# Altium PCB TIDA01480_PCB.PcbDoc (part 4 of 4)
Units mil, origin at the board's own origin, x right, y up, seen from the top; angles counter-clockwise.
Board outline 2500 x 3500 mil, 6 copper layers (Top Layer, GND Upper, Signal Layer 1, Signal Layer 2, GND Lower, Bottom Layer), stack 63.4 mil thick; 332 components, 140 nets, 983 pads, 692 vias.
Unrouted connection lines stored in the file: 17.
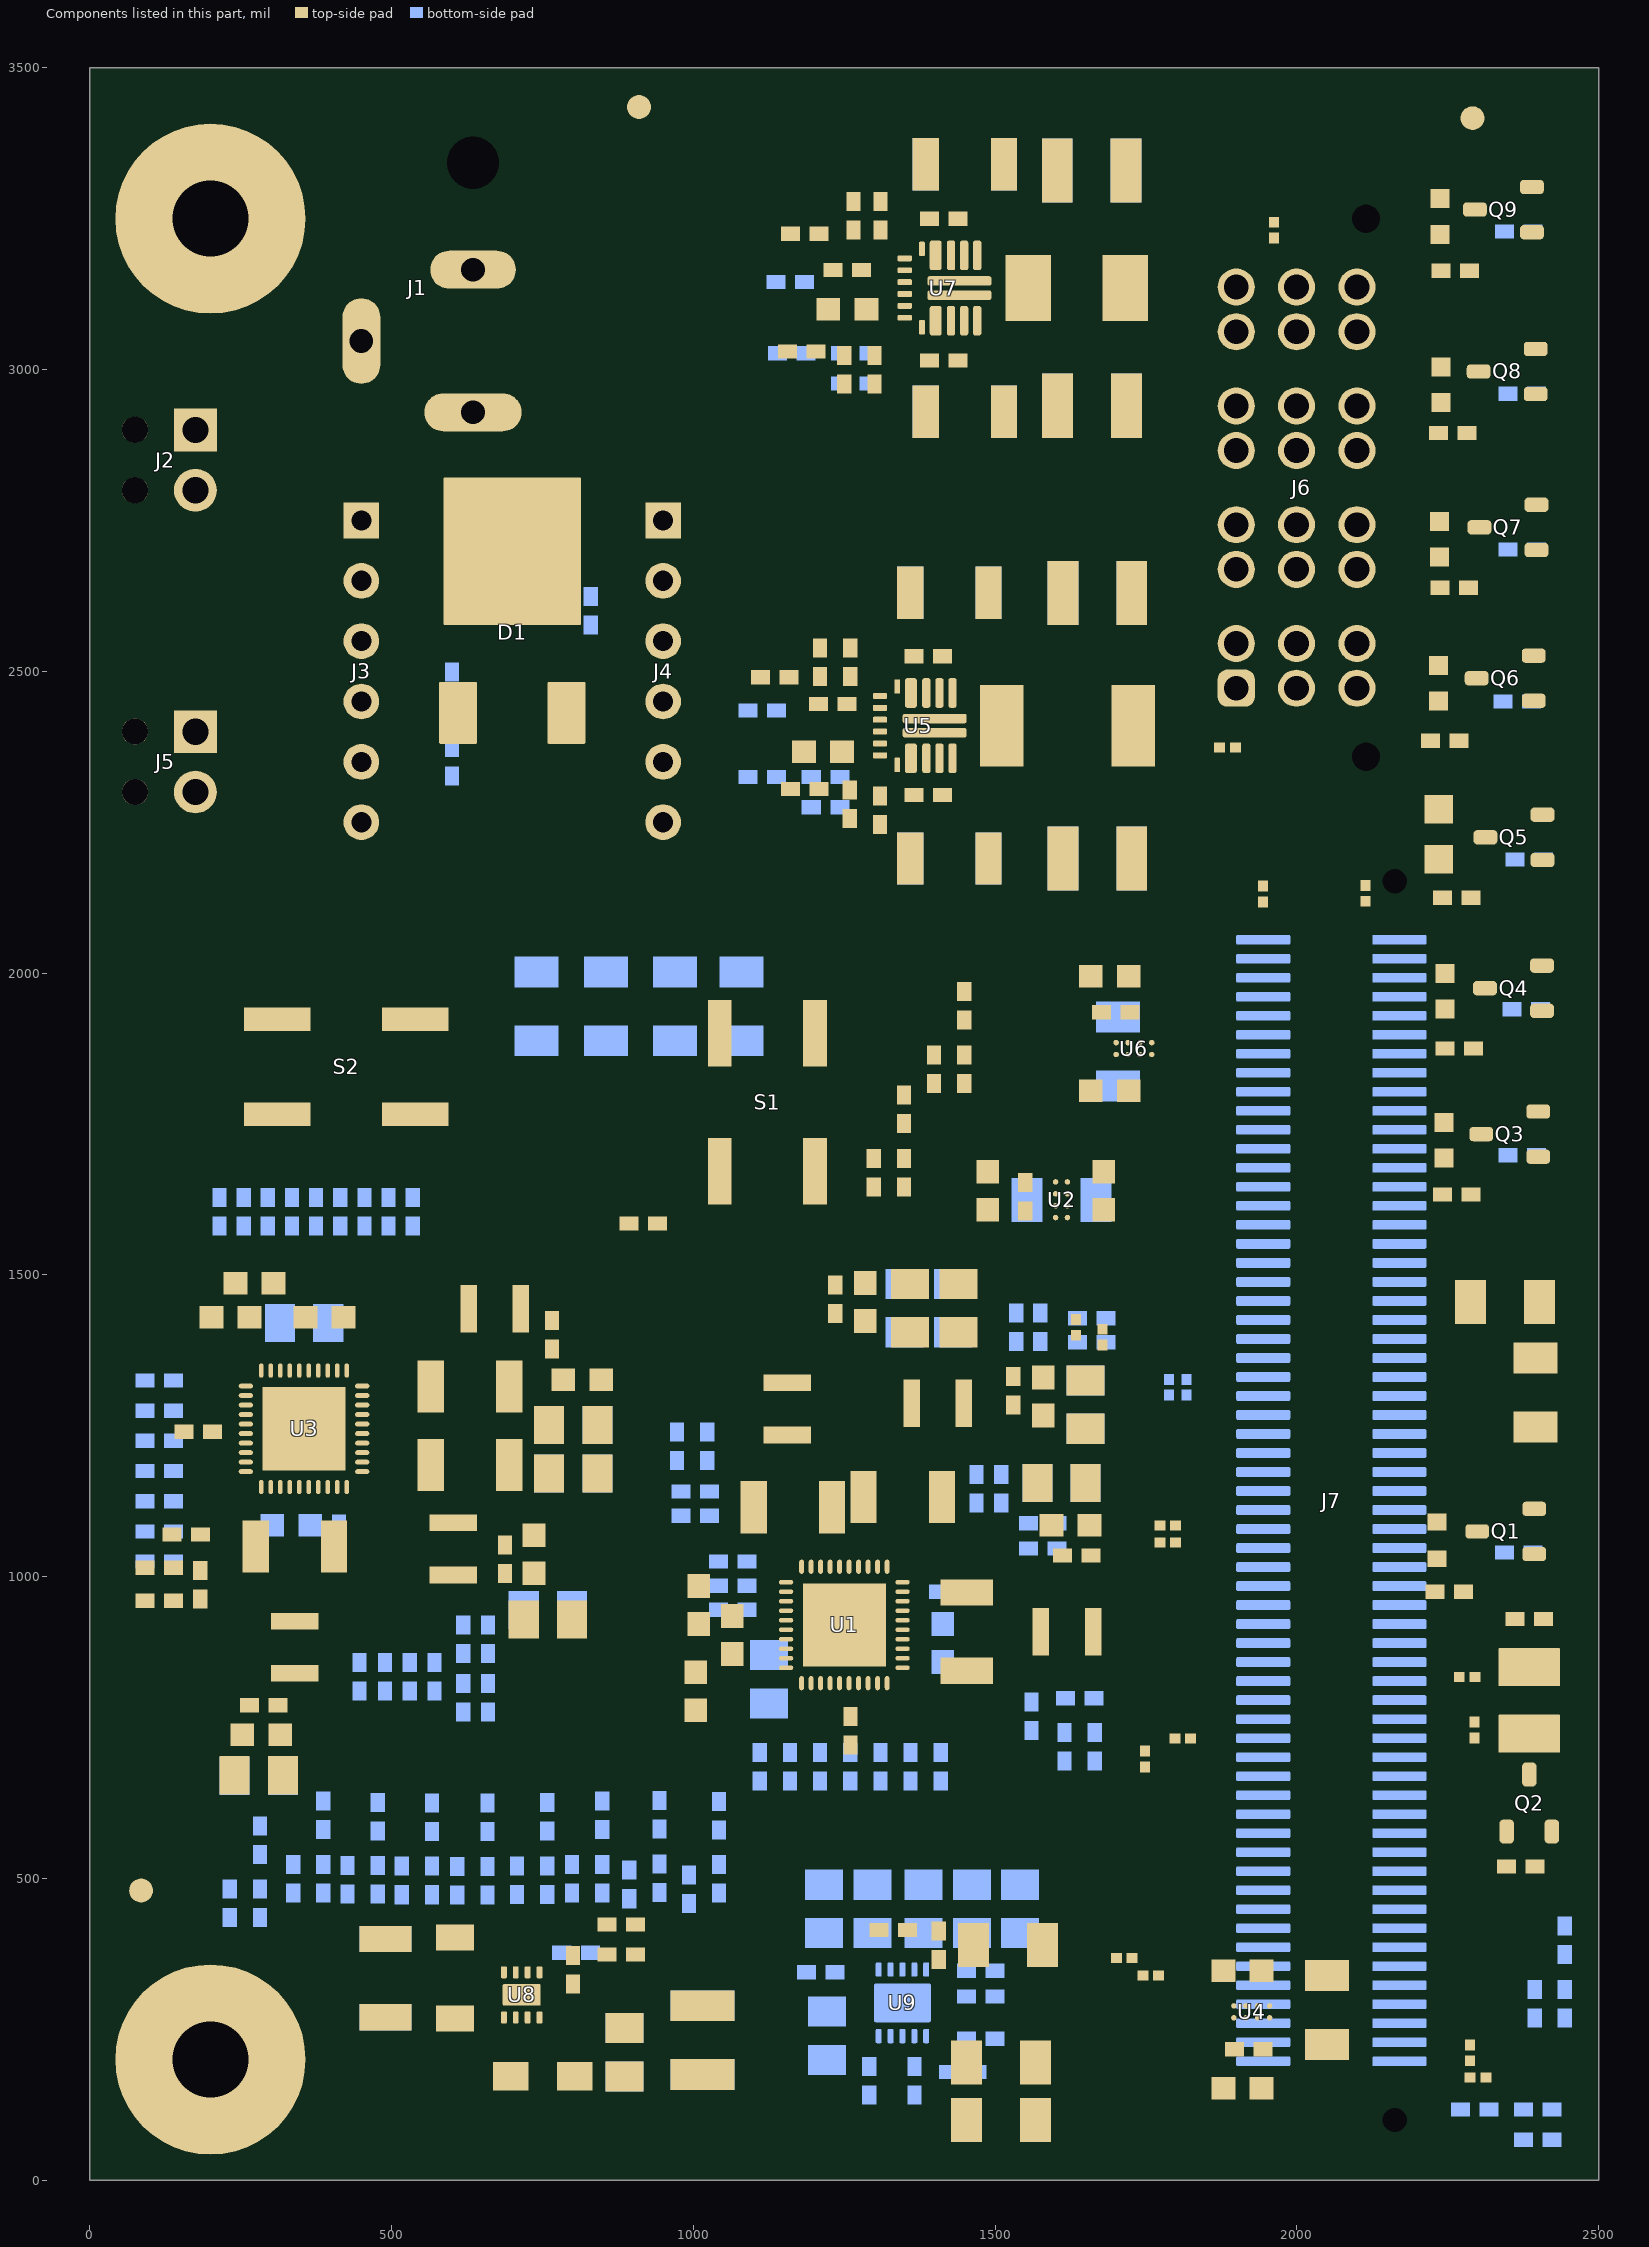
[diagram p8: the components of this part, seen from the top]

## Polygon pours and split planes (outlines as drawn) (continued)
GND on Top Layer "TOP_LAYER_GND_P100" (solid, remove dead copper, pour order 100): 325,1178 325,1135 299,1109 263,1109 240,1086 240,962 297,962 297,1067 310.28,1080.28 338,1108 338,1178
GND on Top Layer "TOP_LAYER_GND_P098" (solid, remove dead copper, pour order 98): 324,1355 324,1311 325,1310 386,1310 386,1360 396,1370 430,1370 469,1409 469,1462 389,1462 389,1393 359,1363 355,1363 355,1326 354,1327 340,1327 340,1355
LDO2B on Top Layer "TOP_LAYER_LDO2B_P096" (solid, remove dead copper, pour order 96): 310,1327 310,1373 334,1397 334,1514.89 382,1515.08 382,1397 345,1360 329,1360 324,1355 324,1327
VSYS on Top Layer "TOP_LAYER_VSYS_P094" (solid, remove dead copper, pour order 94): 307,1328 307,1373 332,1398 332,1545 270,1545 270,1449.98 293,1449.98 293,1328
NetL6_1 on Top Layer "TOP_LAYER_NETL6_1_P092" (solid, remove dead copper, pour order 92): 439,1216 439,1227 440,1228 503,1228 540,1191 540,1136.86 546.93,1129.93 642,1129.93 642,1039 560,1039 532.5,1066.5 503,1096 503,1195 482,1216
NetL4_1 on Top Layer "TOP_LAYER_NETL4_1_P090" (solid, remove dead copper, pour order 90): 438,1274 438,1263 439,1262 498,1262 537,1301 537,1363 576,1402 643.43,1402 643.43,1490 540,1490 520,1452 520,1399 500,1379 500,1293 481,1274
VSYS on Top Layer "TOP_LAYER_VSYS_P088" (solid, remove dead copper, pour order 88): 439,1258 439,1230 509,1230 543,1196 543,1140 609,1140 609,1360 540,1360 540,1300 498,1258
VDCDC2_B on Top Layer "TOP_LAYER_VDCDC2_B_P044" (solid, remove dead copper, pour order 44): 295,860 295,640 383,640 383,780 390,796 392,796 392,843 390,843 383,860
VCC_1or2A on Top Layer "TOP_LAYER_VCC_1OR2A_P060" (solid, remove dead copper, pour order 60): 770,220 770,100 1095.63,100 1094,101.63 1094,220
GND on Top Layer "TOP_LAYER_GND_P086" (solid, remove dead copper, pour order 86): 1070,322 1070,240 959,240 946,227 833,227 810,250 770,250 770,293 787,310 950,310 962,322
NetL9_1 on Top Layer "TOP_LAYER_NETL9_1_P062" (solid, remove dead copper, pour order 62): 698,284 698,241 697,241 651,195 650,195 650,100 740,100 740,242 732,250 715,256 715,284
GND on Top Layer "TOP_LAYER_GND_P084" (solid, remove dead copper, pour order 84): 505,191 445,236 445,297 530,297 559,326 695,326 695,248 638,191
VSYS on Top Layer "TOP_LAYER_VSYS_P028" (solid, remove dead copper, pour order 28): 430,477 430,430 430,340 621,340 631,330 715,330 715,380 704,380 612.99,477
GND on Top Layer "TOP_LAYER_GND_P080" (solid, remove dead copper, pour order 80): 1720,1310 1505,1310 1505,1035 1568,1035 1568,1030 1588,1010 1633,1010 1633,1068 1632,1069 1632,1093.5 1620,1105.5 1620,1125.5 1620,1203 1719,1203 1720,1204
VDCDC2_A on Top Layer "TOP_LAYER_VDCDC2_A_P058" (solid, remove dead copper, pour order 58): 1639,851 1639,1051 1625,1065 1625,1193 1731,1193 1731,877 1705,851
GND on Top Layer "TOP_LAYER_GND_P078" (solid, remove dead copper, pour order 78): 1334,902 1334,891 1336,889 1380,889 1389,880 1389,843 1432,800 1557,800 1557,866 1429,866 1384,903 1336,903
VSYS on Top Layer "TOP_LAYER_VSYS_P022" (solid, remove dead copper, pour order 22): 1333,924 1389,924 1430,952 1555,952 1555,1030 1439,1030 1384,975 1384,949 1368,933 1333,933
NetL2_1 on Top Layer "TOP_LAYER_NETL2_1_P056" (solid, remove dead copper, pour order 56): 1334,907 1385,907 1400,898 1433,870 1463,870 1520,870 1520,869.2 1529.2,860 1591.41,860 1591.41,950 1499,950 1499,943 1426,943 1388,918 1334,918
VSYS on Top Layer "TOP_LAYER_VSYS_P014" (solid, remove dead copper, pour order 14): 1167,869 1167,860 1151,860 1129.62,852.32 1082,852.32 1022.7,852.32 990,870 953,870 953,892 1045.82,892 1083.23,892 1083.23,880.77 1092,872 1149.31,872 1151.31,870 1166,870
VLDO2A_3V3 on Top Layer "TOP_LAYER_VLDO2A_3V3_P054" (solid, remove dead copper, pour order 54): 1166,885 1166,876 1088.87,876 1081.46,897 947.42,897 947.42,956 1090,956 1090,919 1094,915 1096,913 1120,906 1141,885
VLDO1A_1V8 on Top Layer "TOP_LAYER_VLDO1A_1V8_P052" (solid, remove dead copper, pour order 52): 1165,854 1022,854 1022,875.02 950,875.02 950,807 1120,807 1133,807 1165,839
VDCDC3_A on Top Layer "TOP_LAYER_VDCDC3_A_P042" (solid, remove dead copper, pour order 42): 1430.59,1363.77 1430.59,1244.11 1500,1243.88 1500,1305 1505,1310 1555,1310 1565,1300 1608.54,1300 1621.46,1287.09 1621.46,1285 1720,1285 1720,1365 1431.82,1365
NetL3_1 on Top Layer "TOP_LAYER_NETL3_1_P050" (solid, remove dead copper, pour order 50): 1387.28,1330.31 1387.28,1244.23 1383,1194 1383,1091 1280,1045.21 1280,1000 1262,1000 1262,1058.74 1308,1089 1310,1135 1346,1244.23 1346,1330.31
VDCDC1_A on Top Layer "TOP_LAYER_VDCDC1_A_P034" (solid, remove dead copper, pour order 34): 1045,1330 1045,1423.19 1086.81,1465 1256.32,1465 1271.32,1450 1480,1450 1480,1369 1260,1369 1260,1330
VSYS on Top Layer "TOP_LAYER_VSYS_P018" (solid, remove dead copper, pour order 18): 1415,3160 1385,3160 1385,3220 1350,3255 1350,3485 1485,3485 1485,3294.88 1465.12,3275 1430,3275 1430,3225 1420,3225 1415,3220
GND on Top Layer "TOP_LAYER_GND_P006" (solid, remove dead copper, pour order 6): 1415,3160 1415,3225 1423,3233 1423,3273 1430,3280 1500,3280 1500,3485 1710,3485 1710,3275 1660,3225 1490,3225 1480,3165
VCC_8A on Top Layer "TOP_LAYER_VCC_8A_P000" (solid, remove dead copper, pour order 0): 1670,3485 1670,2886.85 1771,2886.85 1771,3485
GND on Top Layer "TOP_LAYER_GND_P002" (solid, remove dead copper, pour order 2): 1415,3110 1415,3045 1428.19,3031.81 1429.27,3031.81 1429.27,2990.73 1430,2990 1500,2990 1500,2758 1710,2758 1710,2995 1660,3045 1490,3045 1480,3105
VSYS on Top Layer "TOP_LAYER_VSYS_P024" (solid, remove dead copper, pour order 24): 1415,3105 1390,3105 1390,3045 1355,3010 1355,2780 1495,2780 1495,2965.12 1470.12,2990 1435,2990 1435,3040 1425,3040 1415,3045
NetC68_2 on Top Layer "TOP_LAYER_NETC68_2_P048" (solid, remove dead copper, pour order 48): 1385,3155 1480,3155 1490,3165 1490,3185 1510,3205 1595,3205 1595,3065 1510,3065 1490,3085 1490,3104.1 1479.1,3115 1385,3115
NetC51_2 on Top Layer "TOP_LAYER_NETC51_2_P046" (solid, remove dead copper, pour order 46): 1345,2430 1440,2430 1450,2440 1450,2460 1470,2480 1550,2480 1550,2340 1470,2340 1450,2360 1450,2379.1 1439.1,2390 1345,2390
GND on Top Layer "TOP_LAYER_GND_P076" (solid, remove dead copper, pour order 76): 1562.76,1635 1450,1635 1450,1725 1725,1725 1725,1650 1580,1650
VCC_PSPLL on Top Layer "TOP_LAYER_VCC_PSPLL_P036" (solid, remove dead copper, pour order 36): 1612,1644.13 1612,1564.3 1709.3,1564.3 1732,1587 1732,1640 1661.85,1640 1661.3,1639.45 1656.61,1644.13
VDCDC1_A on Top Layer "TOP_LAYER_VDCDC1_A_P030" (solid, remove dead copper, pour order 30): 1565,1628 1581.13,1644.13 1608,1644.13 1608,1564 1450,1564.21 1450,1628
VSYS on Top Layer "TOP_LAYER_VSYS_P020" (solid, remove dead copper, pour order 20): 1263,1000 1263,1059.36 1306.46,1088.75 1306.46,1225 1203.18,1225 1210,1075 1220,1065 1237,1048 1237,1000
LDO1B__or__VPS_MTRAVTT on Top Layer "TOP_LAYER_LDO1B__OR__VPS_MTRAVTT_P040" (solid, remove dead copper, pour order 40): 288,1449 288,1329 278,1329 262,1355 198,1355 198,1449
GND on Top Layer "TOP_LAYER_GND_P070" (solid, remove dead copper, pour order 70): 283,846 283,609 182,609 182,846
VSYS on Top Layer "TOP_LAYER_VSYS_P026" (solid, remove dead copper, pour order 26): 1375,2380 1350,2380 1350,2320 1315,2285 1315,2055 1455,2055 1455,2240.12 1430.12,2265 1395,2265 1395,2315 1385,2315 1375,2320
GND on Top Layer "TOP_LAYER_GND_P064" (solid, remove dead copper, pour order 64): 1375,2385 1375,2320 1388.19,2306.81 1389.27,2306.81 1389.27,2265.73 1390,2265 1460,2265 1460,2060 1670,2060 1670,2270 1620,2320 1450,2320 1440,2380
VCC_12A on Top Layer "TOP_LAYER_VCC_12A_P032" (solid, remove dead copper, pour order 32): 1685,2687 1685,1878 1780,1878 1780,2687
GND on Top Layer "TOP_LAYER_GND_P066" (solid, remove dead copper, pour order 66): 1375,2435 1375,2500 1388.19,2513.19 1389.27,2513.19 1389.27,2554.27 1390,2555 1460,2555 1460,2760 1670,2760 1670,2550 1620,2500 1450,2500 1440,2440
VSYS on Top Layer "TOP_LAYER_VSYS_P016" (solid, remove dead copper, pour order 16): 1375,2435 1345,2435 1345,2495 1310,2530 1310,2760 1450,2760 1450,2574.88 1425.12,2550 1390,2550 1390,2500 1380,2500 1375,2495
VSYS on Top Layer "TOP_LAYER_VSYS_P162" (solid, remove dead copper, pour order 162): 0,3500 1625,3500 1625,965 510,965 510,1830 0,1830
VCC_12A_LS3 on Top Layer "TOP_LAYER_VCC_12A_LS3_P104" (solid, remove dead copper, pour order 104): 1684,1878 1684,1776 1825,1776 1899,1791.29 1899,1817.12 1856,1850 1759,1850 1745,1878
VCC_12A on Top Layer "TOP_LAYER_VCC_12A_P106" (solid, remove dead copper, pour order 106): 2120,2599 2151,2568 2151,2450 2120,2419 2120,2415 1830,2415 1776,2361 1776,2649 1826,2599
VCC_8A on Top Layer "TOP_LAYER_VCC_8A_P108" (solid, remove dead copper, pour order 108): 2104,3189 2135,3158 2135,3040 2104,3009 2104,3005 1814,3005 1760,2951 1760,3239 1810,3189
GND on Top Layer "TOP_LAYER_GND_P110" (solid, remove dead copper, pour order 110): 2113,2998 2157,2954 2157,2655 2115,2613 1831,2613 1795,2649 1795,2695 1662,2695 1663,2696 1663,2880 1779,2880 1780,2879 1780,2951 1827,2998
VDCDC3_B on Top Layer "TOP_LAYER_VDCDC3_B_P112" (solid, remove dead copper, pour order 112): 550,1030 550,980 620,910 765,910 767,908 767,1015 752,1030
VDCDC1_B on Top Layer "TOP_LAYER_VDCDC1_B_P114" (solid, remove dead copper, pour order 114): 691,1490 690,1489 690,1402 788,1402 820,1370 820,1308 810,1298 810,1085 900,1085 900,1130 900,1410 853,1410 773,1490
GND on Top Layer "TOP_LAYER_GND_P116" (solid, remove dead copper, pour order 116): 645,1393 648,1396 782,1396 810,1368 810,1311 811,1310 800,1299 800,1080 850,1030 850,901 851,900 771,900 770,901 770,1028 758,1040 660,1040 660,1226 645,1241
NetD1_1 on Top Layer "TOP_LAYER_NETD1_1_P008" (solid, remove dead copper, pour order 8): 1000,2800 815,2800 815,2640 750,2575 690,2485 578.35,2485 578.35,2370 900,2370 900,2500 1000,2500
NetJ3_1 on Top Layer "TOP_LAYER_NETJ3_1_P010" (solid, remove dead copper, pour order 10): 25,2350 300,2350 450,2500 460,2500 500,2540 500,2820 490,2810 275,2810 275,2705 200,2630 115,2630 25,2540
VSYS on Bottom Layer "BOTTOM_LAYER_VSYS_P186" (solid, remove dead copper, pour order 186): 0,3500 2500,3500 2500,0 0,0
VCC_1or2A on Bottom Layer "BOTTOM_LAYER_VCC_1OR2A_P148" (solid, remove dead copper, pour order 148): 1995,245 2005,255 2005,330 1995,340 1810,340 1715,245 1715,240 1825,240 1830,245
VDCDC2_B on Bottom Layer "BOTTOM_LAYER_VDCDC2_B_P140" (solid, remove dead copper, pour order 140): 1319,87 1626,87 1643,104 1935,104 2074,243 2245.29,243 2262,226.29 2262,198 2245.29,181.29 2120,181.29 1972,32 1319,32
GND on Bottom Layer "BOTTOM_LAYER_GND_P082" (solid, remove dead copper, pour order 82): 1689,1278 1570,1278 1515.5,1223.5 1515.5,1192.5 1545,1163 1545,1123 1569,1123 1579.6,1123 1619,1123 1619,1200 1631,1212 1688,1212 1689,1213
GND on Bottom Layer "BOTTOM_LAYER_GND_P166" (solid, remove dead copper, pour order 166): 325,1105.12 255,1105 255,1010 240,995 240,960 295,960 295,1036.3 325,1066.3
GND on Bottom Layer "BOTTOM_LAYER_GND_P170" (solid, remove dead copper, pour order 170): 750,326 750,290 688,290 683,285 683,235 633,185 495,185 444,236 444,330 454,340 619,340 633,326
GND on Bottom Layer "BOTTOM_LAYER_GND_P172" (solid, remove dead copper, pour order 172): 283,837 283,608 182,608 182,837
VDCDC3_B on Bottom Layer "BOTTOM_LAYER_VDCDC3_B_P174" (solid, remove dead copper, pour order 174): 685,986 749,986 760,975 760,875 750,865 685,865
GND on Bottom Layer "BOTTOM_LAYER_GND_P176" (solid, remove dead copper, pour order 176): 840,986 776,986 765,975 765,875 785,855 840,855
VDCDC2_B on Bottom Layer "BOTTOM_LAYER_VDCDC2_B_P182" (solid, remove dead copper, pour order 182): 295,815 295,649 383,649 383,780 392,789 392,815
GND on GND Upper "GND_UPPER_GND_P152" (solid, remove dead copper, pour order 152): 0,3500 2500,3500 2500,0 0,0
GND on GND Lower "GND_LOWER_GND_P156" (solid, remove dead copper, pour order 156): 0,3500 2500,3500 2500,0 0,0
VSYS on Signal Layer 2 "SIGNAL_LAYER_2_VSYS_P164" (solid, remove dead copper, pour order 164): 0,3500 2500,3500 2500,0 0,0
VSYS on Signal Layer 1 "SIGNAL_LAYER_1_VSYS_P184" (solid, remove dead copper, pour order 184): 0,3500 2500,3500 2500,0 0,0

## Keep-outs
Keep-Out Layer:
  text ".Layer_Name" at 577,-858.49 h60

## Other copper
Top Layer:
  rectangle net VSYS: 2220,1405 2345,1585
  rectangle net GND: 1837,326 1899,372
  rectangle net GND: 1825,121 1913,237
  rectangle net VTT: 1555,380 1660,435
  rectangle net VDCDC2_B: 482,32 1418,87
  text ".Layer_Name" at 577,-858.49 h60
Bottom Layer:
  rectangle net VDCDC3_A: 1618,1300 1726,1354
  rectangle net VSYS: 439,373 656,447.17
  rectangle net VSYS: 1312,2587 1381,2713
  rectangle net VDCDC1_A: 1444,1565 1574,1659
  rectangle net VCC_PSPLL: 1638,1565 1714,1667
  rectangle net VCC_12A_LS3: 1661,1785 1786,1849
  rectangle net VCC_12A: 1666,1901 1784,1976.3
  rectangle net VSYS: 1318,2112 1387,2236
  rectangle net GND: 1463,2093 1655,2298
  rectangle net VCC_12A: 1687,2092 1779,2243.15
  rectangle net VCC_8A: 1684,2875 1770,2994
  rectangle net GND: 1485,2814 1663,3046
  rectangle net VSYS: 1354,2815 1440,3040
  rectangle net VSYS: 1350,3226 1414,3437
  rectangle net GND: 1489,3263 1649,3440
  rectangle net VCC_8A: 1671,3270 1774,3424
  rectangle net GND: 1222,1460 1464,1550
  rectangle net VDCDC1_A: 1233,1376 1464,1451
  rectangle net VDCDC2_A: 1625,1118 1730,1187
  rectangle net VDCDC1_B: 800,1125 893,1300
  rectangle net GND: 675,1105 790,1297.46
  rectangle net VCC_12A: 1696,2535 1785,2683
  rectangle net GND: 1460,2510 1640,2760
  text ".Layer_Name" at 577,-858.49 h60

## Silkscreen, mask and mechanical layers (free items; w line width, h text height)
Top Overlay:
  drawing of 163 lines, arcs and shapes, not listed
  text "2.5mm ID, 5.5mm OD" at 834,3360 h40 r270
  text "5V, 6A min. (30W)" at 878,3336 h40 r270
  text "8A Sns (Near)" at 1915,3195 h40 r90
  text "LDO1-A PG" at 2467,3139 h40 r90
  text "5V IN (+)" at 100,2990 h40
  text "8A Discrete Buck" at 1080,2960 h50 r90
  text "U7 PG (8A)" at 2465,2875 h40 r90
  text "GND (-)" at 120,2685 h40
  text "U5 PG (12A)" at 2464,2624 h40 r90
  text "HV Input (+)" at 110,2490 h40
  text "VDDR PG" at 2471,2418 h40 r90
  text "Near" at 1909,2343 h40 r270
  text "12A Buck Sns" at 1971,2340.74 h40 r270
  text "AIC insert" at 560,2315 h60
  text "(HV--> 5V Pre-reg)" at 515,2265 h50
  text "Far" at 1885,2200 h40 r270
  text "GND (-)" at 110,2190 h40
  text "(DDR Term)" at 2471,2185 h40 r90
  text "U9 PG" at 2473,2071 h40 r90
  text "'.PRJ_Number'.PCB_Rev-" at 30,2065 h108.27
  text "12A Discrete Buck" at 1070,2017.09 h50
  text "8A Sns (Far)" at 2080,2005 h40 r90
  text "EN LS3" at 1235,1965 h40
  text "U8 PG" at 2474,1917 h40 r90
  text "DCDC1-A PG" at 2475,1609 h40 r90
  text "PMIC2 (B)" at 90,1565 h60
  text "PMIC1 (A)" at 1005,1565 h60
  text "EN LS1" at 1305,1565 h40
  text "5V" at 2275,1349 h40
  text "3.3V" at 2313,1246 h40 r90
  text "VLED Sel" at 2250,1225 h40 r90
  text "DCDC2-A Sns" at 1734.26,1175 h40
  text "Near" at 1745,1130 h40
  text "Far" at 1744.16,1005 h40
  text "VSYS PG" at 2484,986 h40 r90
  text "Near" at 2210,775 h40
  text "Near" at 1755,745 h40 r90
  text "VSYS Fault" at 2485,725 h40 r90
  text "Far" at 1805,670 h40
  text "Far" at 2260,670 h40 r90
  text "DCDC3-B Sns" at 2185,585 h40 r90
  text "DCDC1-B Sns" at 1685,572 h40
  text "VTT Res Div" at 1330,545 h50
  text "1 or 2A Discrete Buck" at 545.35,475 h50
  text "1o2A Dscrt Sns" at 1650,427 h40
  text "Far" at 1780,361 h40 r90
  text "Near" at 1630,330 h40
  text "Far" at 2340,251 h40 r90
  text "VDDR Sel" at 1616,231 h40
  text "LED Indicators" at 2470,230 h40 r90
  text "U4 Bypass" at 2135,195 h40 r90
  text "1o2A dscrt" at 1615,160 h40
  text "Near" at 2340,117.21 h40
  text "DCDC2-B Sns" at 2255,115 h40 r90
  text "DCDC2-B" at 1615,112 h40
  text ".Layer_Name" at 577,-858.49 h60
Bottom Overlay:
  lines w4: 121,1360 121,1398 ; 136,1595 153,1612 172,1612 ; 180,560 190,550 210,530 ; 305,350 315,340 370,340 380,350 ; 345,330 355,320 365,310 380,295 ; 370,975 405,975 415,965 ; 415,265 415,350 425,360 425,410 ; 416,955 421,960 426,965 486,965 491,965 496,960 ; 420,430 455,430 465,440 ; 505,965 510,970 570,970 575,970 580,965 ; 530,975 530,990 ; 565,345 575,335 575,325 575,265 ; 580,1117 580,1107 596,1091 596,1090 ; 600,350 610,340 665,340 675,350 ; 631,1036 639.5,1027.5 ; 635,285 635,330 ; 685,345 695,335 750,335 760,345 ; 715,255 715,325 ; 750,1822 750,1842 ; 790,735 800,745 855,745 865,735 ; 850,441 850,435 860,425 ; 850,755 850,810 860,820 865,825 ; 855,1820 855,1837 ; 890,755 900,765 955,765 965,755 ; 925,775 925,820 ; 975,748.98 985,758.98 1040,758.98 1050,748.98 ; 975,1820 975,1840 ; 985.3,825 996.3,814 996.3,770 ; 1053,1179 1059,1173 1060,1173 ; 1060,1163 1060,1173 ; 1076,1189 1070,1183 1060,1173 ; 1080,1818 1080,1835 ; 1179,968 1187,968 1192,963 1203,952 ; 1241,842 1254,842 1274.78,821.22 1274.78,813 ; 1408,1197 1419,1186 1438,1186 ; 1418,1085 1435,1068 1516,1068 ; 1572,867 1572,847 1584,835 ; 1577,828 1584,835 ; 1594,835 1584,835 ; 1597,1483 1606,1474 1623,1474 ; 1699,1473 1761,1473 ; 1785,1266.94 1785,1284.47 ; 1815,1268 1815,1284.6 ; 1845.52,1217 1845.52,1417 ; 2250,182 2266,166 ; 2344,390 2354,380 ; 670,1645 670,2100 685,2115 775,2115 1010,2115 1130,2115 1150,2095 1150,1645 1140,1635 680,1635 670,1645
  lines w10: 1110,97 1665,97 1665,581 1110,581 1110,97
  text "VIO Select" at 1040,2125 h60
  text "U6 Bypass" at 1770,1795 h40 r270
  text "(3.3V)" at 826,1699 h40 r270
  text "U2 Bypass" at 1690,1690 h40
  text "LDO2-A" at 860,1670 h40 r270
  text "DCDC2-B" at 737,1652 h40 r270
  text "DCDC3-A" at 1066,1651 h40 r270
  text "1o2A dscrt" at 964,1645 h40 r270
  text "DCDC3-A FB" at 1772,1467 h40 r270
  text "PMIC2 (B) IOs" at 101,1407 h40 r270
  text "Far" at 1805,1210 h40 r270
  text "DCDC3-A Sns" at 1850.69,1208.17 h40 r270
  text "DCDC1-A Comp" at 1430,1203 h40
  text "DCDC1-A FB" at 1081,1192 h40 r270
  text "Near" at 1770,1185 h40 r270
  text "DCDC3-B FB" at 569,1125 h40 r270
  text "VSYS Comp" at 1428,1095 h40
  text "VDDR Comp" at 519,994 h40 r270
  text "LDO1-A Comp" at 365,955 h40
  text "DCDC2-A FB" at 1729,872 h40
  text "PMIC1 (A) IOs" at 1209,841 h40 r270
  text "EN DCDC2-A" at 865,835 h40 r270
  text "EN DCDC1-A" at 910,835 h40 r270
  text "EN LDOs-A" at 970,835 h40 r270
  text "EN LDOs-B" at 148,573 h40 r270
  text "EN LS2" at 2320,400 h40 r270
  text "EN DDR Term" at 2235,190 h40 r270
  text "EN DCDC3-B" at 376,66 h40 r270
  text "EN DCDC1-B" at 559,43 h40 r270
  text "EN 1o2A Dscrt" at 625,43 h40 r270
  text "EN DCDC2-B" at 415,42 h40 r270
  text "EN DCDC3-A" at 693,37 h40 r270
  text ".Layer_Name" at 577,-858.49 h60
Top Paste:
  text ".Layer_Name" at 577,-858.49 h60
Bottom Paste:
  text ".Layer_Name" at 577,-858.49 h60
Top Solder:
  text ".Layer_Name" at 577,-858.49 h60
  text ".Layer_Name" at 577,-858.49 h60
Bottom Solder:
  text ".Layer_Name" at 577,-858.49 h60
Drill Guide:
  text ".Layer_Name" at 577,-858.49 h60
M1 Board Outline:
  the board outline again, w10
  text ".Layer_Name" at 577,-858.49 h60
M2 Board Dimensions:
  rectangle: 125,-400 500,-275
  rectangle: 0,-275 125,-150
  lines w7: 0,-275 1000,-275 ; 125,-400 125,-150 ; 250,-400 250,-150 ; 500,-400 500,-150 ; 750,-400 750,-150 ; 0,-400 0,-150 1000,-150 1000,-400 0,-400
  text ".Layer_Name" at 577,-858.49 h60
M3 3D STEP Top:
  text ".Layer_Name" at 577,-858.49 h60
M4 3D STEP Bottom:
  text ".Layer_Name" at 577,-858.49 h60
M5 Assembly Top:
  lines w10: -292,-930.17 6308,-930.17 ; -292,-726.83 6310,-726.83 ; -292,-523.5 -292,-1133.5 3713,-1133.5 6310,-1133.5 6310,-523.5 -291.5,-523.5 -291.5,-1133.5 1284,-1133.5 ; 2173,-1133.5 2173,-523.5 ; 3440,-726.83 3440,-523.5 ; 4280,-726.83 4280,-523.5 ; 4902,-1140 4902,-937.17
  text "COMPONENTS MARKED 'DNP' SHOULD NOT BE POPULATED." at 1153.5,-318.5 h60
  text "ASSEMBLY VARIANT:" at 1153,-434 h60
  text ".VariantName" at 2189,-434 h60
  text "PCB VIEWED FROM TOP SIDE" at -228.5,-655.67 h60
  text "BOARD #:" at 2248,-655.67 h60
  text ".PRJ_Number" at 2793.5,-655.67 h60
  text "REV:" at 3638,-655.67 h60
  text ".PCB_Rev" at 3929.5,-655.67 h60
  text "SVN REV:" at 4476,-655.67 h60
  text ".VersionControl_RevNumber" at 4982,-655.67 h60
  text "TID #:" at 2248,-859 h60
  text ".TID" at 2793.5,-859 h60
  text "PLOT NAME =" at -228.5,-1064.34 h60
  text ".plot_File_Name" at 577,-1064.34 h60
  text "GENERATED    :" at 2250,-1064.34 h60
  text ".Print_Date" at 3119.5,-1064.34 h60
  text ".Print_Time" at 3848.5,-1064.34 h60
  text "TEXAS INSTRUMENTS" at 5113,-1064.34 h60
M6 Assembly Bottom:
  lines w10: -292.5,-727.33 6309.5,-727.33 ; -290.5,-930.67 6309.5,-930.67 ; 1115.5,-1140.5 1115.5,-937.67 ; 1737.5,-727.33 1737.5,-524 ; 2577.5,-727.33 2577.5,-524 ; 3844.5,-1134 3844.5,-524 ; 4733.5,-1134 6309,-1134 6309,-524 -292.5,-524 -292.5,-1134 2304.5,-1134 6309.5,-1134 6309.5,-524
  text "COMPONENTS MARKED 'DNP' SHOULD NOT BE POPULATED." at 6102,-318 h60
  text ".VariantName" at 5058,-434 h60
  text "ASSEMBLY VARIANT:" at 6097,-434 h60
  text ".VersionControl_RevNumber" at 1035.5,-656.17 h60
  text "SVN REV:" at 1541.5,-656.17 h60
  text ".PCB_Rev" at 2088,-656.17 h60
  text "REV:" at 2379.5,-656.17 h60
  text ".PRJ_Number" at 3224,-656.17 h60
  text "BOARD #:" at 3769.5,-656.17 h60
  text "PCB VIEWED FROM BOTTOM SIDE" at 6246,-656.17 h60
  text ".TID" at 3224,-859.5 h60
  text "TID #:" at 3769.5,-859.5 h60
  text "TEXAS INSTRUMENTS" at 904.5,-1064.84 h60
  text ".Print_Time" at 2169,-1064.84 h60
  text ".Print_Date" at 2898,-1064.84 h60
  text "GENERATED    :" at 3767.5,-1064.84 h60
  text ".plot_File_Name" at 5440.5,-1064.84 h60
  text "PLOT NAME =" at 6246,-1064.84 h60
M9 Title Sheet:
  drawing of 57 lines, arcs and shapes, not listed
  text "1" at 739.84,8036.5 h70
  text "2" at 3235.5,8036.5 h70
  text "3" at 5724.84,8036.5 h70
  text "4" at 8231.51,8036.5 h70
  text "5" at 10730.5,8036.5 h70
  text "6" at 13235.5,8036.5 h70
  text "A" at -416.5,6893.5 h70
  text "A" at 14383.5,6893.5 h70
  text "B" at -416.5,4513.5 h70
  text "B" at 14383.5,4513.5 h70
  text "C" at -416.5,2138.5 h70
  text "C" at 14383.5,2138.5 h70
  text "PROJECT TITLE:" at 11343.5,277.5 h45
  text ".PRJ_Title" at 11393.5,144.17 h70
  text "DESIGNED FOR:" at 11343.5,-23.5 h45
  text ".PRJ_Customer" at 11393.5,-163.5 h70
  text "D" at -416.5,-231.5 h70
  text "D" at 14383.5,-231.5 h70
  text "FILE NAME:" at 11343.5,-323.5 h45
  text ".PCB_File_Name_No_Path" at 11393.5,-443.5 h70
  text "Texas Instruments (TI) and/or its licensors do not warrant the accuracy or completeness of this specification" at 6374,-605.34 h45
  text "ENGINEER:" at 11343.5,-613.5 h45
  text "LAYOUT BY:" at 12848.5,-613.5 h45
  text "or any information contained therein. TI and/or its licensors do not warrant that this design will meet" at 6329.01,-718 h45
  text ".PRJ_Engineer" at 11393.5,-768.49 h70
  text ".PCB_Layout" at 12899,-768.49 h70
  text "the specifications, will be suitable for your application or fit for any particular purpose, or will operate in" at 6329.01,-830.67 h45
  text ".Layer_Name" at 577,-858.49 h60
  text "ALTIUM DESIGNER VERSION:" at 12848.5,-923.5 h45
  text "an implementation. TI and/or its licensors do not warrant that the design is production worthy. You should" at 6329.01,-943.33 h45
  text "completely validate and test your design implementation to confirm the system functionality for your application." at 6374,-1056 h45
  text ".print_Scale" at 11393.5,-1056.83 h70
  text ".Application_BuildNumber" at 12899,-1056.83 h70
  text "1" at 739.84,-1263.5 h70
  text "2" at 3235.5,-1263.5 h70
  text "3" at 5724.84,-1263.5 h70
  text "4" at 8231.51,-1263.5 h70
  text "5" at 10730.5,-1263.5 h70
  text "6" at 13235.5,-1263.5 h70
M10 Fab Notes:
  drawing of 189 lines, arcs and shapes, not listed
  text "DESIGN INFORMATION" at 12382.02,6356.17 h60
  text "MIN. TRACK WIDTH:" at 11737.46,6224.05 h60
  text "4" at 12833.7,6224.05 h60
  text "MIL" at 12988.46,6224.05 h60
  text "MIN. CLEARANCE:" at 11737.46,6099.92 h60
  text "0.2" at 12773.7,6099.93 h60
  text "mm" at 12988.46,6099.92 h60
  text "MIN. VIA PAD SIZE:" at 11737.46,5975.8 h60
  text "14" at 12803.71,5975.8 h60
  text "MIL" at 12988.46,5975.8 h60
  text "0.05mm (2MIL)" at 12432.46,5845.9 h60
  text "MINIMUM ANNULAR RING" at 11408.23,5837.67 h60
  text "EXTERNAL" at 13140.46,5837.67 h60
  text "PER" at 11608.23,5727.55 h60
  text "IPC-D-275 CLASS 2 LEVEL C" at 11828.23,5727.54 h60
  text "MIL, HOLES" at 13316.46,5627.07 h60
  text "+/-" at 12924,5618.48 h60
  text "+/-" at 13778,5618.48 h60
  text "REGISTRATION TOLERANCES:" at 11408.23,5617.42 h60
  text "METAL" at 12608,5617.42 h60
  text "5" at 13184.2,5617.42 h60
  text "3" at 14017.2,5617.42 h60
  text "MIL" at 14133.46,5617.42 h60
  text "HOLE SIZE TOLERANCE (UNLESS OTHERWISE SPECIFIED):" at 11408.23,5519.1 h60
  text "+/-" at 13778,5516.23 h60
  text "3" at 14017.2,5515.17 h60
  text "MIL" at 14133.46,5515.17 h60
  text "MATERIAL:" at 11333.46,5377.52 h60
  text "FR-4 High Tg" at 12319.9,5249 h60
  text "X" at 12175.46,5241.01 h60
  text "FR-408" at 11754.46,5236.49 h60
  text "OTHER" at 13242.46,5236.49 h60
  text "62 MIL (1.6mm) +/-10%" at 12074.56,5093.46 h60
  text "X" at 11954.46,5091.01 h60
  text "THICKNESS:" at 11408.23,5085.24 h60
  text "OTHER" at 13359.46,5085.24 h60
  text "TOLERANCE:" at 11408.23,4946.92 h60
  text "X" at 12256.46,4946.92 h60
  text "ANSI IPC-6012 TYPE 3 CLASS 2" at 12434.48,4946.92 h60
  text "OTHER +/-" at 12434.46,4802.73 h60
  text "BOW & TWIST:" at 11408.23,4657.54 h60
  text "X" at 12256.46,4657.54 h60
  text "ANSI IPC-6012 TYPE 3 CLASS 2" at 12434.48,4657.54 h60
  text "OTHER +/-" at 12434.46,4510.85 h60
  text "DRILLING:" at 11333.46,4380.23 h60
  text "NC_DRILL FILES" at 13094.46,4275.04 h60
  text "REFERENCE:" at 11408.23,4271.1 h60
  text "X" at 12065.46,4271.01 h60
  text "AS SHOWN" at 12243.46,4271.1 h60
  text "X" at 12966.46,4271.1 h60
  text "OTHER" at 13392.46,4128.85 h60
  text "PTH COPPER THICKNESS:" at 11407.91,4125.32 h60
  text "X" at 12547.14,4125.32 h60
  text "20-30 um" at 12675.14,4125.32 h60
  text "BOARD FINISH:" at 11333.46,3977.73 h60
  text "SILKSCREEN:" at 11488.68,3867.6 h60
  text "X" at 12446.46,3867.6 h60
  text "TOP" at 12563.46,3867.6 h60
  text "X" at 12956.46,3867.6 h60
  text "BOTTOM" at 13074.46,3867.6 h60
  text "SILKSCREEN COLOR:" at 11488.68,3712.41 h60
  text "X" at 12445.46,3712.41 h60
  text "WHITE" at 12563.46,3712.41 h60
  text "OTHER" at 13074.46,3712.41 h60
  text "X" at 12576.46,3568.96 h60
  text "GREEN" at 12694.46,3568.96 h60
  text "OTHER" at 13312.46,3568.96 h60
  text "SOLDER RESIST COLOR:" at 11488.68,3562.1 h60
  text "X" at 12576.46,3414.71 h60
  text "MATTE" at 12694.46,3414.71 h60
  text "SEMI-GLOSS" at 13312,3414.07 h60
  text "IMMERSION GOLD (ENIG)" at 12394.46,3241.94 h60
  text "ENEPIG" at 13732,3234.72 h60
  text "SURFACE FINISH:" at 11333.46,3233.72 h60
  text "X" at 12216.46,3233.72 h60
  text "IMM. TIN/SILVER OR EQUIV" at 11663,3096.4 h60
  text "OTHER" at 13094.46,3092.47 h60
  text "ARRAY/PANEL:" at 11333.46,2937.09 h60
  text "CUT AND TRIM PER M1 BOARD OUTLINE" at 12394.46,2928.87 h60
  text "N.C. ROUTE" at 12394.46,2792.9 h60
  text "X" at 13082.46,2792.9 h60
  text "V. SCORE" at 13260.46,2792.9 h60
  text "CERTIFICATION:" at 11333.46,2663.77 h60
  text "MATERIALS AND WORKMANSHIP FOR ALL PCBS" at 12058.46,2663.77 h60
  text "TO MEET OR EXCEED THE REQUIREMENTS OF:" at 12058.46,2569.71 h60
  text "X" at 11695.97,2441.08 h60
  text "ANSI IPC-A-600F CLASS ->" at 11823.96,2441.08 h60
  text "X" at 13471.97,2441.08 h60
  text "2" at 13581.96,2441.08 h60
  text "1" at 13266.96,2439.58 h60
  text "3" at 13935.96,2439.58 h60
  text "X" at 12507.97,2293.39 h60
  text "RoHS" at 12635.96,2293.39 h60
  text "OTHER" at 13280.36,2293.39 h60
  text "PER ORDER" at 13677.42,2293.39 h60
  text "ALL BOARDS MUST MEET OR EXCEED UL94-V0 REQUIREMENTS." at 11361,2139.57 h60
  text "PCB MUST BEAR THE UL94V-0 UL REGISTERED MATERIAL ID NUMBER" at 11361,2023.5 h60
  text "ADDITIONAL REQUIREMENTS:" at 11333.46,1854.08 h60
  text "MICROSECTION:" at 11408.23,1746.95 h60
  text "YES" at 12313.96,1746.95 h60
  text "REQUIRED" at 13175.46,1602.62 h60
  text "BARE BOARD ELEC. TEST:" at 11408.23,1599.76 h60
  text "NONE" at 12713.96,1599.76 h60
  text "X" at 13057.46,1599.76 h60
  text "PER ORDER" at 13767.46,1599.76 h60
  text "XX MIL VIAS REQUIRE NON-CONDUCTIVE FILL AND PLANARIZE" at 11576.38,1394.82 h59
  text "XX MIL VIAS REQUIRE CONDUCTIVE FILL AND PLANARIZE" at 11584.38,1290.84 h60
  text "OUTER XX MIL VIAS REQUIRE 50 OHM SINGLE-ENDED IMPEDANCE" at 11583.39,1127.46 h58
  text "LAYER 2 & 3 (INNER LAYERS) XX MIL WIDE, XX MIL SPACE / TRACES REQUIRE 100 OHM DIFFERENTIAL IMPEDANCE" at 11575.39,891.74 h60
  text ".Layer_Name" at 577,-858.49 h60
M11 Gerber Information:
  lines w10: -292,-930.17 6308,-930.17 ; -292,-726.83 6310,-726.83 ; -292,-523.5 -292,-1133.5 3713,-1133.5 6310,-1133.5 6310,-523.5 -291.5,-523.5 -291.5,-1133.5 1284,-1133.5 ; 2173,-1133.5 2173,-523.5 ; 3440,-726.83 3440,-523.5 ; 4280,-726.83 4280,-523.5 ; 4902,-1140 4902,-937.17
  text "ALL ARTWORK VIEWED FROM TOP SIDE" at -228.5,-655.67 h60
  text "BOARD #:" at 2248,-655.67 h60
  text ".PRJ_Number" at 2793.5,-655.67 h60
  text "REV:" at 3638,-655.67 h60
  text ".PCB_Rev" at 3929.5,-655.67 h60
  text "SVN REV:" at 4476,-655.67 h60
  text ".VersionControl_RevNumber" at 4982,-655.67 h60
  text "LAYER NAME =" at -228.5,-858.49 h60
  text "TID #:" at 2248,-859 h60
  text ".TID" at 2793.5,-859 h60
  text "PLOT NAME =" at -228.5,-1064.34 h60
  text ".plot_File_Name" at 577,-1064.34 h60
  text "GENERATED    :" at 2250,-1064.34 h60
  text ".Print_Date" at 3119.5,-1064.34 h60
  text ".Print_Time" at 3848.5,-1064.34 h60
  text "TEXAS INSTRUMENTS" at 5113,-1064.34 h60
M12 Stackup:
  drawing of 399 lines, arcs and shapes, not listed
  text "Layer" at 6780.74,7840 h60
  text "Name" at 7190.66,7840 h60
  text "Material" at 8130.4,7840 h60
  text "Thickness" at 8990.16,7840 h60
  text "Constant" at 9640,7840 h60
  text "Board Layer Stack" at 10209.86,7840 h60
  text "1" at 6780.74,7720 h60
  text "Top Overlay" at 7190.66,7720 h60
  text "2" at 6780.74,7600 h60
  text "Top Solder" at 7190.66,7600 h60
  text "Solder Resist" at 8130.4,7600 h60
  text "0.40mil" at 8990.16,7600 h60
  text "3.5" at 9640,7600 h60
  text "3" at 6780.74,7480 h60
  text "Top Layer" at 7190.66,7480 h60
  text "Copper" at 8130.4,7480 h60
  text "1.40mil" at 8990.16,7480 h60
  text "4" at 6780.74,7360 h60
  text "Dielectric 2" at 7190.66,7360 h60
  text "FR-4" at 8130.4,7360 h60
  text "9.00mil" at 8990.16,7360 h60
  text "4.2" at 9640,7360 h60
  text "5" at 6780.74,7240 h60
  text "GND Upper" at 7190.66,7240 h60
  text "Copper" at 8130.4,7240 h60
  text "1.40mil" at 8990.16,7240 h60
  text "6" at 6780.74,7120 h60
  text "Dielectric 4" at 7190.66,7120 h60
  text "FR-4" at 8130.4,7120 h60
  text "14.00mil" at 8990.16,7120 h60
  text "4.8" at 9640,7120 h60
  text "7" at 6780.74,7000 h60
  text "Signal Layer 1" at 7190.66,7000 h60
  text "Copper" at 8130.4,7000 h60
  text "1.40mil" at 8990.16,7000 h60
  text "8" at 6780.74,6880 h60
  text "Dielectric1" at 7190.66,6880 h60
  text "FR-4" at 8130.4,6880 h60
  text "9.00mil" at 8990.16,6880 h60
  text "4.2" at 9640,6880 h60
  text "9" at 6780.74,6760 h60
  text "Signal Layer 2" at 7190.66,6760 h60
  text "Copper" at 8130.4,6760 h60
  text "1.40mil" at 8990.16,6760 h60
  text "10" at 6780.74,6640 h60
  text "Dielectric 5" at 7190.66,6640 h60
  text "FR-4" at 8130.4,6640 h60
  text "14.00mil" at 8990.16,6640 h60
  text "4.8" at 9640,6640 h60
  text "11" at 6780.74,6520 h60
  text "GND Lower" at 7190.66,6520 h60
  text "Copper" at 8130.4,6520 h60
  text "1.40mil" at 8990.16,6520 h60
  text "12" at 6780.74,6400 h60
  text "Dielectric 3" at 7190.66,6400 h60
  text "FR-4" at 8130.4,6400 h60
  text "9.00mil" at 8990.16,6400 h60
  text "4.2" at 9640,6400 h60
  text "13" at 6780.74,6280 h60
  text "Bottom Layer" at 7190.66,6280 h60
  text "Copper" at 8130.4,6280 h60
  text "1.40mil" at 8990.16,6280 h60
  text "14" at 6780.74,6160 h60
  text "Bottom Solder" at 7190.66,6160 h60
  text "Solder Resist" at 8130.4,6160 h60
  text "0.40mil" at 8990.16,6160 h60
  text "3.5" at 9640,6160 h60
  text "15" at 6780.74,6040 h60
  text "Bottom Overlay" at 7190.66,6040 h60
  text ".Layer_Name" at 577,-858.49 h60
M13 Component Bodies Top:
  text ".Layer_Name" at 577,-858.49 h60
M14 Component Bodies Bottom:
  text ".Layer_Name" at 577,-858.49 h60
M15 Courtyards Top:
  text ".Layer_Name" at 577,-858.49 h60
M16 Courtyards Bottom:
  text ".Layer_Name" at 577,-858.49 h60
Drill Drawing:
  drawing of 157 lines, arcs and shapes, not listed
  text "Symbol" at 3800,3350 h72
  text "Count" at 4085.83,3350 h72
  text "Hole Size" at 4372.07,3350 h72
  text "Plated" at 4946.54,3350 h72
  text "Hole Type" at 5190.88,3350 h72
  text "Drill Layer Pair" at 5551.3,3350 h72
  text "Via/Pad" at 6260.14,3350 h72
  text "Hole Tolerance (+)" at 6548.71,3350 h72
  text "676" at 4085.83,3250.55 h60
  text "7.90mil (0.201mm)" at 4372.07,3250.55 h60
  text "PTH" at 4946.54,3250.55 h60
  text "Round" at 5190.88,3250.55 h60
  text "Top Layer - Bottom Layer" at 5551.3,3250.55 h60
  text "Via" at 6260.14,3250.55 h60
  text "24" at 4085.83,3151.1 h60
  text "40.95mil (1.040mm)" at 4372.07,3151.1 h60
  text "PTH" at 4946.54,3151.1 h60
  text "Round" at 5190.88,3151.1 h60
  text "Top Layer - Bottom Layer" at 5551.3,3151.1 h60
  text "Pad" at 6260.14,3151.1 h60
  text "16" at 4085.83,3051.65 h60
  text "7.87mil (0.200mm)" at 4372.07,3051.65 h60
  text "PTH" at 4946.54,3051.65 h60
  text "Round" at 5190.88,3051.65 h60
  text "Top Layer - Bottom Layer" at 5551.3,3051.65 h60
  text "Via" at 6260.14,3051.65 h60
  text "A" at 3778.4,3041.66 h44.2
  text "12" at 4085.83,2952.2 h60
  text "33.47mil (0.850mm)" at 4372.07,2952.2 h60
  text "PTH" at 4946.54,2952.2 h60
  text "Round" at 5190.88,2952.2 h60
  text "Top Layer - Bottom Layer" at 5551.3,2952.2 h60
  text "Pad" at 6260.14,2952.2 h60
  text "4" at 4085.83,2852.75 h60
  text "43.31mil (1.100mm)" at 4372.07,2852.75 h60
  text "NPTH" at 4946.54,2852.75 h60
  text "Round" at 5190.88,2852.75 h60
  text "Top Layer - Bottom Layer" at 5551.3,2852.75 h60
  text "Pad" at 6260.14,2852.75 h60
  text "4" at 4085.83,2753.3 h60
  text "43.31mil (1.100mm)" at 4372.07,2753.3 h60
  text "PTH" at 4946.54,2753.3 h60
  text "Round" at 5190.88,2753.3 h60
  text "Top Layer - Bottom Layer" at 5551.3,2753.3 h60
  text "Pad" at 6260.14,2753.3 h60
  text "2" at 4085.83,2653.85 h60
  text "39.37mil (1.000mm)" at 4372.07,2653.85 h60
  text "PTH" at 4946.54,2653.85 h60
  text "Slot" at 5190.88,2653.85 h60
  text "Top Layer - Bottom Layer" at 5551.3,2653.85 h60
  text "Pad" at 6260.14,2653.85 h60
  text "2" at 4085.83,2554.4 h60
  text "40.16mil (1.020mm)" at 4372.07,2554.4 h60
  text "NPTH" at 4946.54,2554.4 h60
  text "Round" at 5190.88,2554.4 h60
  text "Top Layer - Bottom Layer" at 5551.3,2554.4 h60
  text "Pad" at 6260.14,2554.4 h60
  text "2" at 4085.83,2454.95 h60
  text "46.85mil (1.190mm)" at 4372.07,2454.95 h60
  text "NPTH" at 4946.54,2454.95 h60
  text "Round" at 5190.88,2454.95 h60
  text "Top Layer - Bottom Layer" at 5551.3,2454.95 h60
  text "Pad" at 6260.14,2454.95 h60
  text "2" at 4085.83,2355.5 h60
  text "125.98mil (3.200mm)" at 4372.07,2355.5 h60
  text "PTH" at 4946.54,2355.5 h60
  text "Round" at 5190.88,2355.5 h60
  text "Top Layer - Bottom Layer" at 5551.3,2355.5 h60
  text "Pad" at 6260.14,2355.5 h60
  text "1" at 4085.83,2256.05 h60
  text "39.37mil (1.000mm)" at 4372.07,2256.05 h60
  text "PTH" at 4946.54,2256.05 h60
  text "Slot" at 5190.88,2256.05 h60
  text "Top Layer - Bottom Layer" at 5551.3,2256.05 h60
  text "Pad" at 6260.14,2256.05 h60
  text "1" at 4085.83,2156.6 h60
  text "86.61mil (2.200mm)" at 4372.07,2156.6 h60
  text "NPTH" at 4946.54,2156.6 h60
  text "Round" at 5190.88,2156.6 h60
  text "Top Layer - Bottom Layer" at 5551.3,2156.6 h60
  text "Pad" at 6260.14,2156.6 h60
  text "746 Total" at 4085.83,2057.15 h60
  text "Slot definitions :" at 3800,1977.53 h60
  text "Routed Path Length" at 4242.9,1977.53 h60
  text "= Calculated from tool start centre position to tool end centre position." at 4774.61,1977.53 h60
  text "Hole Length" at 4242.9,1927.75 h60
  text "= Routed Path Length + Tool Size = Slot length as defined in the PCB layout" at 4575.01,1927.75 h60
  text ".Layer_Name" at 577,-858.49 h60
M17 Embedded Cavity:
  text ".Layer_Name" at 577,-858.49 h60
M18 Embedded Assembly:
  text ".Layer_Name" at 577,-858.49 h60
M19 Embedded Keepout:
  text ".Layer_Name" at 577,-858.49 h60

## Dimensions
0,0 to 2500,0 on M2 Board Dimensions
0,0 to 0,3500 on M2 Board Dimensions
0,-400 to 1000,-400 on M2 Board Dimensions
